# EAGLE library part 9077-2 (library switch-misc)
MARQUARDT SWITCH 9077.0200 Distributor: Buerklin
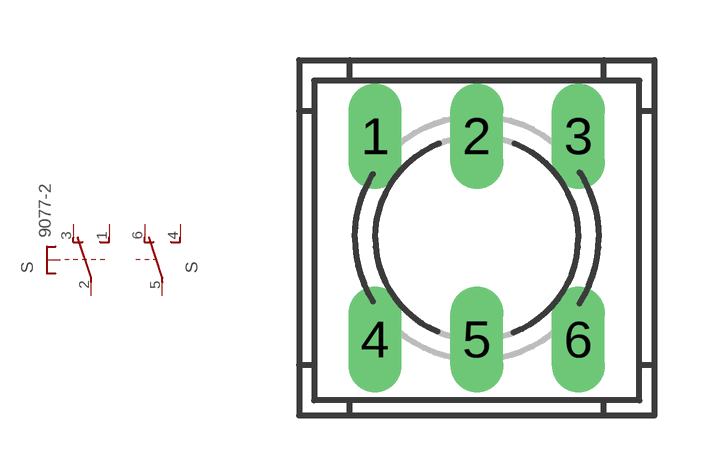
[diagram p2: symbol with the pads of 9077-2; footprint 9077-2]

Designator prefix S; gates 1=TSU- 2=U-2

## 9077-2  [9077-2]
1  1:S  pas
2  1:P  pas
3  1:O  pas
4  2:S  pas
5  2:P  pas
6  2:O  pas

## Footprint 9077-2 (pad centres in mm)
MARQUARDT SWITCH 9077.0200 Distributor: Buerklin
drill 0.813 long: 1 -2.54,2.54; 2 0,2.54; 3 2.54,2.54; 4 -2.54,-2.54; 5 0,-2.54; 6 2.54,-2.54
